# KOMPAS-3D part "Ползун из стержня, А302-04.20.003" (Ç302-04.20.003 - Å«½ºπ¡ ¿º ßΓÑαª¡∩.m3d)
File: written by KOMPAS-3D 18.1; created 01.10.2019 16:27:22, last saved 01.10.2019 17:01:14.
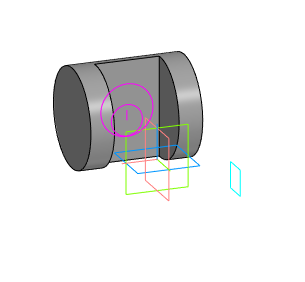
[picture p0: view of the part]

Document properties: Полное имя файла: D:\Мембранные насосы\Мембранный электропривод\А302-00.00.000 - ASTRA-302 (МЭ200)\3Д ПВХ\А302-04.20.003 - Ползун из стержня.m3d

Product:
- Part/product: Ползун из стержня  | designation А302-04.20.003
    Масса: 2.44562

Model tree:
1. Эскиз:2  (with: Операция выдавливания:3)
2. Средняя плоскость:1  (with: Операция выдавливания:3)
3. Эскиз:3
4. Элемент выдавливания:1
     Расстояние 1 = 90
5. Эскиз:4  (with: Элемент выдавливания:1)
6. Элемент выдавливания:2
     Расстояние 1 = 52

Referenced files in D:\Мембранные насосы\Мембранный электропривод\А302-00.00.000 - ASTRA-302 (МЭ200)\3Д ПВХ\: А302-01.00.000  - Мембранный насос ASTRA-302 ПВХ.a3d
